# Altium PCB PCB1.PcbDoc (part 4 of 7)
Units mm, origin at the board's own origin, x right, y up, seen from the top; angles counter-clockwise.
Board outline 139.9 x 46.81 mm, 2 copper layers (Top Layer, Bottom Layer); 0 components, 100 nets, 100 pads, 0 vias.
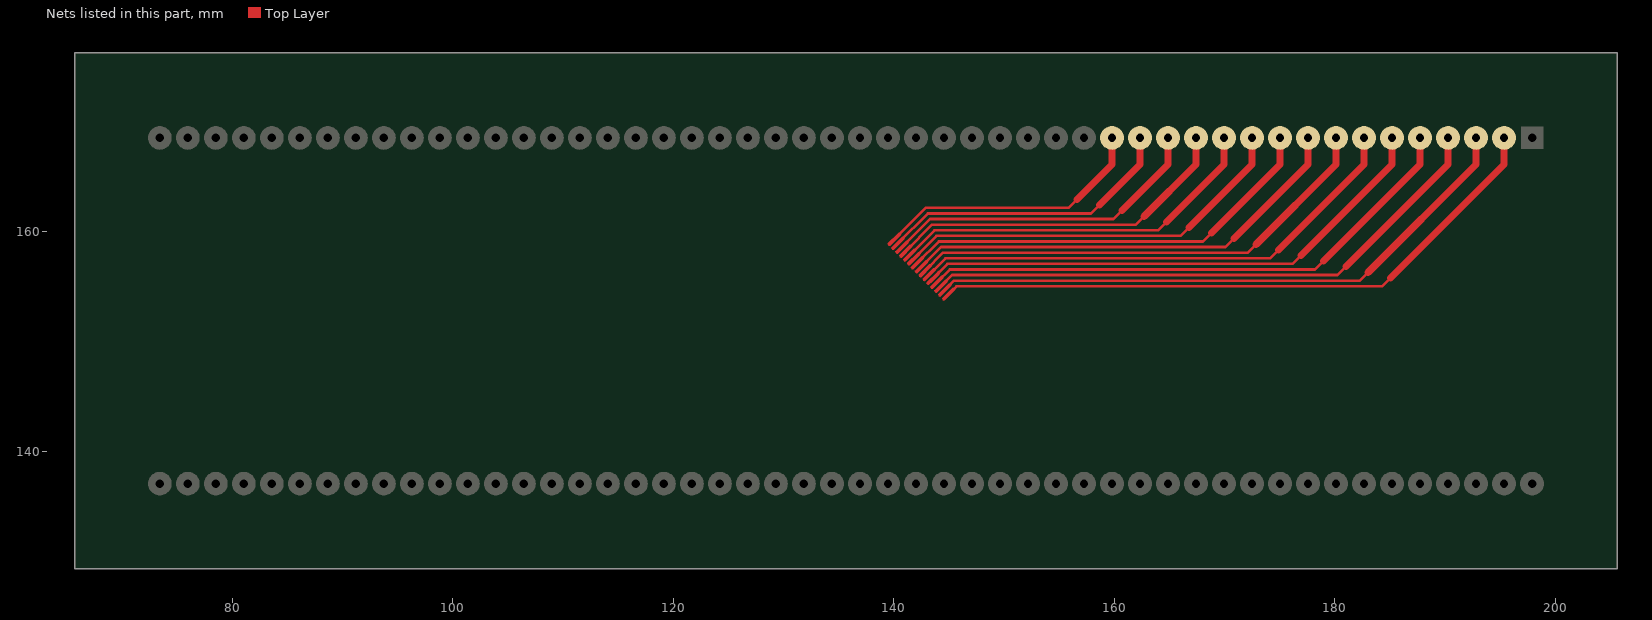
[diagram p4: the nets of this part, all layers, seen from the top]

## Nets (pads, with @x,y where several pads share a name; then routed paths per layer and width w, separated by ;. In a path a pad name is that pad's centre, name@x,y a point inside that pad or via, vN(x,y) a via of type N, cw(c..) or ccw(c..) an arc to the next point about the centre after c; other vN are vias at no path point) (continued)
$Net44: pad.1@159.787,168.455 | length 48.9
  Top Layer w0.03: 139.475,158.8 139.731,158.8 ; 139.475,158.815 139.746,158.815 ; 139.477,158.831 139.762,158.831 ; 139.48,158.785 139.716,158.785 ; 139.487,158.77 139.701,158.77 ; 139.498,158.754 139.686,158.754 ; 139.503,158.876 139.807,158.876 ; 139.51,158.739 139.67,158.739 ; 139.518,158.892 139.823,158.892 ; 139.526,158.724 139.655,158.724 ; 139.533,158.907 139.838,158.907 ; 139.548,158.709 139.637,158.709 ; 139.548,158.922 139.853,158.922 ; 139.564,158.937 139.868,158.937 ; 139.579,158.953 139.884,158.953 ; 139.594,158.968 139.899,158.968 ; 139.609,158.983 139.914,158.983 ; 139.625,158.998 139.929,158.998 ; 139.64,159.014 139.945,159.014 ; 139.655,159.029 139.96,159.029 ; 139.67,159.044 139.975,159.044 ; 139.686,159.059 139.99,159.059 ; 139.701,159.075 140.006,159.075 ; 139.716,159.09 140.021,159.09 ; 139.731,159.105 140.036,159.105 ; 139.746,159.12 140.051,159.12 ; 139.762,159.135 140.067,159.135 ; 139.777,158.846 139.48,158.846 ; 139.777,159.151 140.082,159.151 ; 139.792,158.861 139.487,158.861 ; 139.792,159.166 140.097,159.166 ; 139.807,159.181 140.115,159.181 ; 139.823,159.196 140.13,159.196 ; 139.838,159.212 140.145,159.212 ; 139.853,159.227 140.161,159.227 ; 139.868,159.242 140.176,159.242 ; 139.884,159.257 140.191,159.257 ; 139.899,159.273 140.206,159.273 ; 139.914,159.288 140.221,159.288 ; 139.929,159.303 140.237,159.303 ; 139.945,159.318 140.252,159.318 ; 139.96,159.334 140.267,159.334 ; 139.978,159.349 140.282,159.349 ; 139.993,159.364 140.298,159.364 ; 140.008,159.379 140.313,159.379 ; 140.023,159.395 140.328,159.395 ; 140.039,159.41 140.343,159.41 ; 140.054,159.425 140.359,159.425 ; 140.069,159.44 140.374,159.44 ; 140.084,159.456 140.389,159.456 ; 140.1,159.471 140.404,159.471 ; 140.115,159.486 140.42,159.486 ; 140.13,159.501 140.435,159.501 ; 140.145,159.516 140.45,159.516 ; 140.161,159.532 140.465,159.532 ; 140.176,159.547 140.481,159.547 ; 140.191,159.562 140.496,159.562 ; 140.206,159.577 140.511,159.577 ; 140.221,159.593 140.526,159.593 ; 140.237,159.608 140.542,159.608 ; 140.252,159.623 140.557,159.623 ; 140.267,159.638 140.572,159.638 ; 140.282,159.654 140.587,159.654 ; 140.298,159.669 140.597,159.669 ; 140.313,159.684 140.605,159.684 ; 140.328,159.699 140.608,159.699 ; 140.343,159.715 140.61,159.715 ; 140.359,159.73 140.608,159.73 ; 140.374,159.745 140.602,159.745 ; 140.389,159.76 140.592,159.76 ; 140.404,159.776 140.582,159.776 ; 140.42,159.791 140.567,159.791 ; 140.435,159.806 140.552,159.806 ; 140.455,159.821 140.529,159.821 ; 139.48,158.846 139.487,158.861 ; 139.48,158.846 139.472,158.813 139.475,158.795 139.48,158.78 139.5,158.749 139.528,158.721 139.559,158.701 139.574,158.696 139.592,158.694 139.625,158.701 139.637,158.709 ; 139.487,158.861 139.498,158.874 140.445,159.816 140.458,159.824 140.491,159.831 140.508,159.829 140.524,159.824 140.554,159.804 140.582,159.776 ; 139.637,158.709 140.585,159.651 140.595,159.664 140.602,159.679 140.61,159.712 140.608,159.73 ; 140.582,159.776 140.602,159.745 ; 140.602,159.745 140.608,159.73
  Top Layer w0.241: 140.041,159.262 142.881,162.105 155.85,162.105 156.612,162.867
  Top Layer w0.635: 156.612,162.867 159.787,166.042 pad.1@159.787,168.455
$Net45: pad.1@162.327,168.455 | length 51.2
  Top Layer w0.03: 139.828,158.447 140.084,158.447 ; 139.828,158.462 140.1,158.462 ; 139.83,158.478 140.115,158.478 ; 139.833,158.432 140.069,158.432 ; 139.84,158.417 140.054,158.417 ; 139.851,158.401 140.039,158.401 ; 139.856,158.523 140.161,158.523 ; 139.863,158.386 140.023,158.386 ; 139.871,158.539 140.176,158.539 ; 139.879,158.371 140.008,158.371 ; 139.886,158.554 140.191,158.554 ; 139.901,158.356 139.99,158.356 ; 139.901,158.569 140.206,158.569 ; 139.917,158.584 140.221,158.584 ; 139.932,158.6 140.237,158.6 ; 139.947,158.615 140.252,158.615 ; 139.962,158.63 140.267,158.63 ; 139.978,158.645 140.282,158.645 ; 139.993,158.661 140.298,158.661 ; 140.008,158.676 140.313,158.676 ; 140.023,158.691 140.328,158.691 ; 140.039,158.706 140.343,158.706 ; 140.054,158.721 140.359,158.721 ; 140.069,158.737 140.374,158.737 ; 140.084,158.752 140.389,158.752 ; 140.1,158.767 140.404,158.767 ; 140.115,158.782 140.42,158.782 ; 140.13,158.493 139.833,158.493 ; 140.13,158.798 140.435,158.798 ; 140.145,158.508 139.84,158.508 ; 140.145,158.813 140.45,158.813 ; 140.161,158.828 140.468,158.828 ; 140.176,158.843 140.483,158.843 ; 140.191,158.859 140.498,158.859 ; 140.206,158.874 140.514,158.874 ; 140.221,158.889 140.529,158.889 ; 140.237,158.904 140.544,158.904 ; 140.252,158.92 140.559,158.92 ; 140.267,158.935 140.575,158.935 ; 140.282,158.95 140.59,158.95 ; 140.298,158.965 140.605,158.965 ; 140.313,158.981 140.62,158.981 ; 140.331,158.996 140.635,158.996 ; 140.346,159.011 140.651,159.011 ; 140.361,159.026 140.666,159.026 ; 140.376,159.042 140.681,159.042 ; 140.392,159.057 140.696,159.057 ; 140.407,159.072 140.712,159.072 ; 140.422,159.087 140.727,159.087 ; 140.437,159.102 140.742,159.102 ; 140.453,159.118 140.757,159.118 ; 140.468,159.133 140.773,159.133 ; 140.483,159.148 140.788,159.148 ; 140.498,159.163 140.803,159.163 ; 140.514,159.179 140.818,159.179 ; 140.529,159.194 140.834,159.194 ; 140.544,159.209 140.849,159.209 ; 140.559,159.224 140.864,159.224 ; 140.575,159.24 140.879,159.24 ; 140.59,159.255 140.895,159.255 ; 140.605,159.27 140.91,159.27 ; 140.62,159.285 140.925,159.285 ; 140.635,159.301 140.94,159.301 ; 140.651,159.316 140.95,159.316 ; 140.666,159.331 140.958,159.331 ; 140.681,159.346 140.961,159.346 ; 140.696,159.362 140.963,159.362 ; 140.712,159.377 140.961,159.377 ; 140.727,159.392 140.956,159.392 ; 140.742,159.407 140.945,159.407 ; 140.757,159.423 140.935,159.423 ; 140.773,159.438 140.92,159.438 ; 140.788,159.453 140.905,159.453 ; 140.808,159.468 140.882,159.468 ; 139.833,158.493 139.84,158.508 ; 139.833,158.493 139.825,158.46 139.828,158.442 139.833,158.427 139.853,158.396 139.881,158.368 139.912,158.348 139.927,158.343 139.945,158.34 139.978,158.348 139.99,158.356 ; 139.84,158.508 139.851,158.521 140.798,159.463 140.811,159.471 140.844,159.478 140.862,159.476 140.877,159.471 140.907,159.45 140.935,159.423 ; 139.99,158.356 140.938,159.298 140.948,159.311 140.956,159.326 140.963,159.359 140.961,159.377 ; 140.935,159.423 140.956,159.392 ; 140.956,159.392 140.961,159.377
  Top Layer w0.241: 140.394,158.909 143.082,161.597 157.882,161.597 158.644,162.359
  Top Layer w0.635: 158.644,162.359 162.327,166.042 pad.1@162.327,168.455
$Net46: pad.1@164.867,168.455 | length 53.5
  Top Layer w0.03: 140.181,158.092 140.437,158.092 ; 140.181,158.107 140.453,158.107 ; 140.183,158.122 140.468,158.122 ; 140.186,158.076 140.422,158.076 ; 140.194,158.061 140.407,158.061 ; 140.204,158.046 140.392,158.046 ; 140.209,158.168 140.514,158.168 ; 140.216,158.031 140.376,158.031 ; 140.224,158.183 140.529,158.183 ; 140.232,158.015 140.361,158.015 ; 140.239,158.198 140.544,158.198 ; 140.254,158 140.343,158 ; 140.254,158.213 140.559,158.213 ; 140.27,158.229 140.575,158.229 ; 140.285,158.244 140.59,158.244 ; 140.3,158.259 140.605,158.259 ; 140.315,158.274 140.62,158.274 ; 140.331,158.29 140.635,158.29 ; 140.346,158.305 140.651,158.305 ; 140.361,158.32 140.666,158.32 ; 140.376,158.335 140.681,158.335 ; 140.392,158.351 140.696,158.351 ; 140.407,158.366 140.712,158.366 ; 140.422,158.381 140.727,158.381 ; 140.437,158.396 140.742,158.396 ; 140.453,158.412 140.757,158.412 ; 140.468,158.427 140.773,158.427 ; 140.483,158.137 140.186,158.137 ; 140.483,158.442 140.788,158.442 ; 140.498,158.153 140.194,158.153 ; 140.498,158.457 140.803,158.457 ; 140.514,158.473 140.821,158.473 ; 140.529,158.488 140.836,158.488 ; 140.544,158.503 140.851,158.503 ; 140.559,158.518 140.867,158.518 ; 140.575,158.534 140.882,158.534 ; 140.59,158.549 140.897,158.549 ; 140.605,158.564 140.912,158.564 ; 140.62,158.579 140.928,158.579 ; 140.635,158.594 140.943,158.594 ; 140.651,158.61 140.958,158.61 ; 140.666,158.625 140.973,158.625 ; 140.684,158.64 140.989,158.64 ; 140.699,158.655 141.004,158.655 ; 140.714,158.671 141.019,158.671 ; 140.729,158.686 141.034,158.686 ; 140.745,158.701 141.05,158.701 ; 140.76,158.716 141.065,158.716 ; 140.775,158.732 141.08,158.732 ; 140.79,158.747 141.095,158.747 ; 140.806,158.762 141.11,158.762 ; 140.821,158.777 141.126,158.777 ; 140.836,158.793 141.141,158.793 ; 140.851,158.808 141.156,158.808 ; 140.867,158.823 141.171,158.823 ; 140.882,158.838 141.187,158.838 ; 140.897,158.854 141.202,158.854 ; 140.912,158.869 141.217,158.869 ; 140.928,158.884 141.232,158.884 ; 140.943,158.899 141.248,158.899 ; 140.958,158.915 141.263,158.915 ; 140.973,158.93 141.278,158.93 ; 140.989,158.945 141.293,158.945 ; 141.004,158.96 141.304,158.96 ; 141.019,158.975 141.311,158.975 ; 141.034,158.991 141.314,158.991 ; 141.05,159.006 141.316,159.006 ; 141.065,159.021 141.314,159.021 ; 141.08,159.036 141.309,159.036 ; 141.095,159.052 141.298,159.052 ; 141.11,159.067 141.288,159.067 ; 141.126,159.082 141.273,159.082 ; 141.141,159.097 141.258,159.097 ; 141.161,159.113 141.235,159.113 ; 140.186,158.137 140.194,158.153 ; 140.186,158.137 140.178,158.104 140.181,158.086 140.186,158.071 140.206,158.041 140.234,158.013 140.265,157.992 140.28,157.987 140.298,157.985 140.331,157.992 140.343,158 ; 140.194,158.153 140.204,158.165 141.151,159.108 141.164,159.115 141.197,159.123 141.215,159.12 141.23,159.115 141.26,159.095 141.288,159.067 ; 140.343,158 141.291,158.942 141.301,158.955 141.309,158.97 141.316,159.003 141.314,159.021 ; 141.288,159.067 141.309,159.036 ; 141.309,159.036 141.314,159.021
  Top Layer w0.241: 140.747,158.554 143.28,161.089 159.914,161.089 160.676,161.851
  Top Layer w0.635: 160.676,161.851 164.867,166.042 pad.1@164.867,168.455
$Net47: pad.1@167.407,168.455 | length 55.9
  Top Layer w0.03: 140.534,157.738 140.79,157.738 ; 140.534,157.754 140.806,157.754 ; 140.536,157.769 140.821,157.769 ; 140.539,157.723 140.775,157.723 ; 140.547,157.708 140.76,157.708 ; 140.557,157.693 140.745,157.693 ; 140.562,157.815 140.867,157.815 ; 140.569,157.678 140.729,157.678 ; 140.577,157.83 140.882,157.83 ; 140.585,157.662 140.714,157.662 ; 140.592,157.845 140.897,157.845 ; 140.608,157.647 140.696,157.647 ; 140.608,157.86 140.912,157.86 ; 140.623,157.876 140.928,157.876 ; 140.638,157.891 140.943,157.891 ; 140.653,157.906 140.958,157.906 ; 140.669,157.921 140.973,157.921 ; 140.684,157.937 140.989,157.937 ; 140.699,157.952 141.004,157.952 ; 140.714,157.967 141.019,157.967 ; 140.729,157.982 141.034,157.982 ; 140.745,157.998 141.05,157.998 ; 140.76,158.013 141.065,158.013 ; 140.775,158.028 141.08,158.028 ; 140.79,158.043 141.095,158.043 ; 140.806,158.059 141.11,158.059 ; 140.821,158.074 141.126,158.074 ; 140.836,157.784 140.539,157.784 ; 140.836,158.089 141.141,158.089 ; 140.851,157.799 140.547,157.799 ; 140.851,158.104 141.156,158.104 ; 140.867,158.119 141.174,158.119 ; 140.882,158.135 141.189,158.135 ; 140.897,158.15 141.204,158.15 ; 140.912,158.165 141.22,158.165 ; 140.928,158.18 141.235,158.18 ; 140.943,158.196 141.25,158.196 ; 140.958,158.211 141.265,158.211 ; 140.973,158.226 141.281,158.226 ; 140.989,158.241 141.296,158.241 ; 141.004,158.257 141.311,158.257 ; 141.019,158.272 141.326,158.272 ; 141.037,158.287 141.342,158.287 ; 141.052,158.302 141.357,158.302 ; 141.067,158.318 141.372,158.318 ; 141.083,158.333 141.387,158.333 ; 141.098,158.348 141.403,158.348 ; 141.113,158.363 141.418,158.363 ; 141.128,158.379 141.433,158.379 ; 141.143,158.394 141.448,158.394 ; 141.159,158.409 141.464,158.409 ; 141.174,158.424 141.479,158.424 ; 141.189,158.44 141.494,158.44 ; 141.204,158.455 141.509,158.455 ; 141.22,158.47 141.524,158.47 ; 141.235,158.485 141.54,158.485 ; 141.25,158.5 141.555,158.5 ; 141.265,158.516 141.57,158.516 ; 141.281,158.531 141.585,158.531 ; 141.296,158.546 141.601,158.546 ; 141.311,158.561 141.616,158.561 ; 141.326,158.577 141.631,158.577 ; 141.342,158.592 141.646,158.592 ; 141.357,158.607 141.657,158.607 ; 141.372,158.622 141.664,158.622 ; 141.387,158.638 141.667,158.638 ; 141.403,158.653 141.669,158.653 ; 141.418,158.668 141.667,158.668 ; 141.433,158.683 141.662,158.683 ; 141.448,158.699 141.651,158.699 ; 141.464,158.714 141.641,158.714 ; 141.479,158.729 141.626,158.729 ; 141.494,158.744 141.611,158.744 ; 141.514,158.76 141.588,158.76 ; 140.539,157.784 140.547,157.799 ; 140.539,157.784 140.531,157.751 140.534,157.733 140.539,157.718 140.559,157.688 140.587,157.66 140.618,157.639 140.633,157.634 140.651,157.632 140.684,157.639 140.696,157.647 ; 140.547,157.799 140.557,157.812 141.504,158.754 141.517,158.762 141.55,158.77 141.568,158.767 141.583,158.762 141.613,158.742 141.641,158.714 ; 140.696,157.647 141.644,158.589 141.654,158.602 141.662,158.617 141.669,158.65 141.667,158.668 ; 141.641,158.714 141.662,158.683 ; 141.662,158.683 141.667,158.668
  Top Layer w0.241: 141.1,158.201 143.48,160.581 161.946,160.581 162.708,161.343
  Top Layer w0.635: 162.708,161.343 167.407,166.042 pad.1@167.407,168.455
$Net48: pad.1@169.947,168.455 | length 58.2
  Top Layer w0.03: 140.887,157.385 141.143,157.385 ; 140.887,157.401 141.159,157.401 ; 140.889,157.416 141.174,157.416 ; 140.892,157.37 141.128,157.37 ; 140.9,157.355 141.113,157.355 ; 140.91,157.34 141.098,157.34 ; 140.915,157.462 141.22,157.462 ; 140.923,157.324 141.083,157.324 ; 140.93,157.477 141.235,157.477 ; 140.938,157.309 141.067,157.309 ; 140.945,157.492 141.25,157.492 ; 140.961,157.294 141.05,157.294 ; 140.961,157.507 141.265,157.507 ; 140.976,157.523 141.281,157.523 ; 140.991,157.538 141.296,157.538 ; 141.006,157.553 141.311,157.553 ; 141.022,157.568 141.326,157.568 ; 141.037,157.584 141.342,157.584 ; 141.052,157.599 141.357,157.599 ; 141.067,157.614 141.372,157.614 ; 141.083,157.629 141.387,157.629 ; 141.098,157.645 141.403,157.645 ; 141.113,157.66 141.418,157.66 ; 141.128,157.675 141.433,157.675 ; 141.143,157.69 141.448,157.69 ; 141.159,157.705 141.464,157.705 ; 141.174,157.721 141.479,157.721 ; 141.189,157.431 140.892,157.431 ; 141.189,157.736 141.494,157.736 ; 141.204,157.446 140.9,157.446 ; 141.204,157.751 141.509,157.751 ; 141.22,157.766 141.527,157.766 ; 141.235,157.782 141.542,157.782 ; 141.25,157.797 141.558,157.797 ; 141.265,157.812 141.573,157.812 ; 141.281,157.827 141.588,157.827 ; 141.296,157.843 141.603,157.843 ; 141.311,157.858 141.618,157.858 ; 141.326,157.873 141.634,157.873 ; 141.342,157.888 141.649,157.888 ; 141.357,157.904 141.664,157.904 ; 141.372,157.919 141.679,157.919 ; 141.39,157.934 141.695,157.934 ; 141.405,157.949 141.71,157.949 ; 141.42,157.965 141.725,157.965 ; 141.436,157.98 141.74,157.98 ; 141.451,157.995 141.756,157.995 ; 141.466,158.01 141.771,158.01 ; 141.481,158.026 141.786,158.026 ; 141.497,158.041 141.801,158.041 ; 141.512,158.056 141.817,158.056 ; 141.527,158.071 141.832,158.071 ; 141.542,158.086 141.847,158.086 ; 141.558,158.102 141.862,158.102 ; 141.573,158.117 141.878,158.117 ; 141.588,158.132 141.893,158.132 ; 141.603,158.147 141.908,158.147 ; 141.618,158.163 141.923,158.163 ; 141.634,158.178 141.939,158.178 ; 141.649,158.193 141.954,158.193 ; 141.664,158.208 141.969,158.208 ; 141.679,158.224 141.984,158.224 ; 141.695,158.239 141.999,158.239 ; 141.71,158.254 142.01,158.254 ; 141.725,158.269 142.017,158.269 ; 141.74,158.285 142.02,158.285 ; 141.756,158.3 142.022,158.3 ; 141.771,158.315 142.02,158.315 ; 141.786,158.33 142.015,158.33 ; 141.801,158.346 142.005,158.346 ; 141.817,158.361 141.994,158.361 ; 141.832,158.376 141.979,158.376 ; 141.847,158.391 141.964,158.391 ; 141.867,158.407 141.941,158.407 ; 140.892,157.431 140.9,157.446 ; 140.892,157.431 140.884,157.398 140.887,157.38 140.892,157.365 140.912,157.335 140.94,157.307 140.971,157.286 140.986,157.281 141.004,157.279 141.037,157.286 141.05,157.294 ; 140.9,157.446 140.91,157.459 141.857,158.401 141.87,158.409 141.903,158.417 141.921,158.414 141.936,158.409 141.966,158.389 141.994,158.361 ; 141.05,157.294 141.997,158.236 142.007,158.249 142.015,158.264 142.022,158.297 142.02,158.315 ; 141.994,158.361 142.015,158.33 ; 142.015,158.33 142.02,158.315
  Top Layer w0.241: 141.453,157.848 143.678,160.073 163.978,160.073 164.74,160.835
  Top Layer w0.635: 164.74,160.835 169.947,166.042 pad.1@169.947,168.455
$Net49: pad.1@172.487,168.455 | length 60.5
  Top Layer w0.03: 141.243,157.032 141.499,157.032 ; 141.243,157.048 141.514,157.048 ; 141.245,157.063 141.53,157.063 ; 141.248,157.017 141.484,157.017 ; 141.255,157.002 141.469,157.002 ; 141.265,156.987 141.453,156.987 ; 141.27,157.109 141.575,157.109 ; 141.278,156.971 141.438,156.971 ; 141.286,157.124 141.591,157.124 ; 141.293,156.956 141.423,156.956 ; 141.301,157.139 141.606,157.139 ; 141.316,156.941 141.405,156.941 ; 141.316,157.154 141.621,157.154 ; 141.331,157.17 141.636,157.17 ; 141.347,157.185 141.651,157.185 ; 141.362,157.2 141.667,157.2 ; 141.377,157.215 141.682,157.215 ; 141.392,157.23 141.697,157.23 ; 141.408,157.246 141.712,157.246 ; 141.423,157.261 141.728,157.261 ; 141.438,157.276 141.743,157.276 ; 141.453,157.291 141.758,157.291 ; 141.469,157.307 141.773,157.307 ; 141.484,157.322 141.789,157.322 ; 141.499,157.337 141.804,157.337 ; 141.514,157.352 141.819,157.352 ; 141.53,157.368 141.834,157.368 ; 141.545,157.078 141.248,157.078 ; 141.545,157.383 141.85,157.383 ; 141.56,157.093 141.255,157.093 ; 141.56,157.398 141.865,157.398 ; 141.575,157.413 141.883,157.413 ; 141.591,157.429 141.898,157.429 ; 141.606,157.444 141.913,157.444 ; 141.621,157.459 141.928,157.459 ; 141.636,157.474 141.944,157.474 ; 141.651,157.49 141.959,157.49 ; 141.667,157.505 141.974,157.505 ; 141.682,157.52 141.989,157.52 ; 141.697,157.535 142.005,157.535 ; 141.712,157.551 142.02,157.551 ; 141.728,157.566 142.035,157.566 ; 141.745,157.581 142.05,157.581 ; 141.761,157.596 142.066,157.596 ; 141.776,157.611 142.081,157.611 ; 141.791,157.627 142.096,157.627 ; 141.806,157.642 142.111,157.642 ; 141.822,157.657 142.126,157.657 ; 141.837,157.672 142.142,157.672 ; 141.852,157.688 142.157,157.688 ; 141.867,157.703 142.172,157.703 ; 141.883,157.718 142.187,157.718 ; 141.898,157.733 142.203,157.733 ; 141.913,157.749 142.218,157.749 ; 141.928,157.764 142.233,157.764 ; 141.944,157.779 142.248,157.779 ; 141.959,157.794 142.264,157.794 ; 141.974,157.81 142.279,157.81 ; 141.989,157.825 142.294,157.825 ; 142.005,157.84 142.309,157.84 ; 142.02,157.855 142.325,157.855 ; 142.035,157.871 142.34,157.871 ; 142.05,157.886 142.355,157.886 ; 142.066,157.901 142.365,157.901 ; 142.081,157.916 142.373,157.916 ; 142.096,157.932 142.375,157.932 ; 142.111,157.947 142.378,157.947 ; 142.126,157.962 142.375,157.962 ; 142.142,157.977 142.37,157.977 ; 142.157,157.992 142.36,157.992 ; 142.172,158.008 142.35,158.008 ; 142.187,158.023 142.335,158.023 ; 142.203,158.038 142.32,158.038 ; 142.223,158.053 142.297,158.053 ; 141.248,157.078 141.255,157.093 ; 141.248,157.078 141.24,157.045 141.243,157.027 141.248,157.012 141.268,156.982 141.296,156.954 141.326,156.933 141.342,156.928 141.359,156.926 141.392,156.933 141.405,156.941 ; 141.255,157.093 141.265,157.106 142.213,158.048 142.226,158.056 142.259,158.064 142.276,158.061 142.292,158.056 142.322,158.036 142.35,158.008 ; 141.405,156.941 142.353,157.883 142.363,157.896 142.37,157.911 142.378,157.944 142.375,157.962 ; 142.35,158.008 142.37,157.977 ; 142.37,157.977 142.375,157.962
  Top Layer w0.241: 141.809,157.495 143.877,159.565 166.01,159.565 166.772,160.327
  Top Layer w0.635: 166.772,160.327 172.487,166.042 pad.1@172.487,168.455
$Net50: pad.1@175.025,168.455 | length 62.9
  Top Layer w0.03: 141.596,156.679 141.852,156.679 ; 141.596,156.695 141.867,156.695 ; 141.598,156.71 141.883,156.71 ; 141.601,156.664 141.837,156.664 ; 141.608,156.649 141.822,156.649 ; 141.618,156.634 141.806,156.634 ; 141.624,156.756 141.928,156.756 ; 141.631,156.618 141.791,156.618 ; 141.639,156.771 141.944,156.771 ; 141.646,156.603 141.776,156.603 ; 141.654,156.786 141.959,156.786 ; 141.669,156.588 141.758,156.588 ; 141.669,156.801 141.974,156.801 ; 141.685,156.816 141.989,156.816 ; 141.7,156.832 142.005,156.832 ; 141.715,156.847 142.02,156.847 ; 141.73,156.862 142.035,156.862 ; 141.745,156.877 142.05,156.877 ; 141.761,156.893 142.066,156.893 ; 141.776,156.908 142.081,156.908 ; 141.791,156.923 142.096,156.923 ; 141.806,156.938 142.111,156.938 ; 141.822,156.954 142.126,156.954 ; 141.837,156.969 142.142,156.969 ; 141.852,156.984 142.157,156.984 ; 141.867,156.999 142.172,156.999 ; 141.883,157.015 142.187,157.015 ; 141.898,156.725 141.601,156.725 ; 141.898,157.03 142.203,157.03 ; 141.913,156.74 141.608,156.74 ; 141.913,157.045 142.218,157.045 ; 141.928,157.06 142.236,157.06 ; 141.944,157.076 142.251,157.076 ; 141.959,157.091 142.266,157.091 ; 141.974,157.106 142.281,157.106 ; 141.989,157.121 142.297,157.121 ; 142.005,157.137 142.312,157.137 ; 142.02,157.152 142.327,157.152 ; 142.035,157.167 142.342,157.167 ; 142.05,157.182 142.358,157.182 ; 142.066,157.197 142.373,157.197 ; 142.081,157.213 142.388,157.213 ; 142.099,157.228 142.403,157.228 ; 142.114,157.243 142.419,157.243 ; 142.129,157.258 142.434,157.258 ; 142.144,157.274 142.449,157.274 ; 142.159,157.289 142.464,157.289 ; 142.175,157.304 142.48,157.304 ; 142.19,157.319 142.495,157.319 ; 142.205,157.335 142.51,157.335 ; 142.22,157.35 142.525,157.35 ; 142.236,157.365 142.54,157.365 ; 142.251,157.38 142.556,157.38 ; 142.266,157.396 142.571,157.396 ; 142.281,157.411 142.586,157.411 ; 142.297,157.426 142.601,157.426 ; 142.312,157.441 142.617,157.441 ; 142.327,157.457 142.632,157.457 ; 142.342,157.472 142.647,157.472 ; 142.358,157.487 142.662,157.487 ; 142.373,157.502 142.678,157.502 ; 142.388,157.518 142.693,157.518 ; 142.403,157.533 142.708,157.533 ; 142.419,157.548 142.718,157.548 ; 142.434,157.563 142.726,157.563 ; 142.449,157.578 142.728,157.578 ; 142.464,157.594 142.731,157.594 ; 142.48,157.609 142.728,157.609 ; 142.495,157.624 142.723,157.624 ; 142.51,157.639 142.713,157.639 ; 142.525,157.655 142.703,157.655 ; 142.54,157.67 142.688,157.67 ; 142.556,157.685 142.673,157.685 ; 142.576,157.7 142.65,157.7 ; 141.601,156.725 141.608,156.74 ; 141.601,156.725 141.593,156.692 141.596,156.674 141.601,156.659 141.621,156.629 141.649,156.601 141.679,156.58 141.695,156.575 141.712,156.573 141.745,156.58 141.758,156.588 ; 141.608,156.74 141.618,156.753 142.566,157.695 142.579,157.703 142.612,157.711 142.629,157.708 142.645,157.703 142.675,157.683 142.703,157.655 ; 141.758,156.588 142.706,157.53 142.716,157.543 142.723,157.558 142.731,157.591 142.728,157.609 ; 142.703,157.655 142.723,157.624 ; 142.723,157.624 142.728,157.609
  Top Layer w0.241: 142.162,157.142 144.077,159.057 168.042,159.057 168.804,159.819
  Top Layer w0.635: 168.804,159.819 175.025,166.042 pad.1@175.025,168.455
$Net51: pad.1@177.565,168.455 | length 65.2
  Top Layer w0.03: 141.949,156.326 142.205,156.326 ; 141.949,156.341 142.22,156.341 ; 141.951,156.357 142.236,156.357 ; 141.954,156.311 142.19,156.311 ; 141.961,156.296 142.175,156.296 ; 141.972,156.281 142.159,156.281 ; 141.977,156.402 142.281,156.402 ; 141.984,156.265 142.144,156.265 ; 141.992,156.418 142.297,156.418 ; 141.999,156.25 142.129,156.25 ; 142.007,156.433 142.312,156.433 ; 142.022,156.235 142.111,156.235 ; 142.022,156.448 142.327,156.448 ; 142.038,156.463 142.342,156.463 ; 142.053,156.479 142.358,156.479 ; 142.068,156.494 142.373,156.494 ; 142.083,156.509 142.388,156.509 ; 142.099,156.524 142.403,156.524 ; 142.114,156.54 142.419,156.54 ; 142.129,156.555 142.434,156.555 ; 142.144,156.57 142.449,156.57 ; 142.159,156.585 142.464,156.585 ; 142.175,156.601 142.48,156.601 ; 142.19,156.616 142.495,156.616 ; 142.205,156.631 142.51,156.631 ; 142.22,156.646 142.525,156.646 ; 142.236,156.662 142.54,156.662 ; 142.251,156.372 141.954,156.372 ; 142.251,156.677 142.556,156.677 ; 142.266,156.387 141.961,156.387 ; 142.266,156.692 142.571,156.692 ; 142.281,156.707 142.589,156.707 ; 142.297,156.722 142.604,156.722 ; 142.312,156.738 142.619,156.738 ; 142.327,156.753 142.634,156.753 ; 142.342,156.768 142.65,156.768 ; 142.358,156.783 142.665,156.783 ; 142.373,156.799 142.68,156.799 ; 142.388,156.814 142.695,156.814 ; 142.403,156.829 142.711,156.829 ; 142.419,156.844 142.726,156.844 ; 142.434,156.86 142.741,156.86 ; 142.452,156.875 142.756,156.875 ; 142.467,156.89 142.772,156.89 ; 142.482,156.905 142.787,156.905 ; 142.497,156.921 142.802,156.921 ; 142.513,156.936 142.817,156.936 ; 142.528,156.951 142.833,156.951 ; 142.543,156.966 142.848,156.966 ; 142.558,156.982 142.863,156.982 ; 142.574,156.997 142.878,156.997 ; 142.589,157.012 142.894,157.012 ; 142.604,157.027 142.909,157.027 ; 142.619,157.043 142.924,157.043 ; 142.634,157.058 142.939,157.058 ; 142.65,157.073 142.955,157.073 ; 142.665,157.088 142.97,157.088 ; 142.68,157.103 142.985,157.103 ; 142.695,157.119 143,157.119 ; 142.711,157.134 143.015,157.134 ; 142.726,157.149 143.031,157.149 ; 142.741,157.164 143.046,157.164 ; 142.756,157.18 143.061,157.18 ; 142.772,157.195 143.071,157.195 ; 142.787,157.21 143.079,157.21 ; 142.802,157.225 143.082,157.225 ; 142.817,157.241 143.084,157.241 ; 142.833,157.256 143.082,157.256 ; 142.848,157.271 143.076,157.271 ; 142.863,157.286 143.066,157.286 ; 142.878,157.302 143.056,157.302 ; 142.894,157.317 143.041,157.317 ; 142.909,157.332 143.026,157.332 ; 142.929,157.347 143.003,157.347 ; 141.954,156.372 141.961,156.387 ; 141.954,156.372 141.946,156.339 141.949,156.321 141.954,156.306 141.974,156.275 142.002,156.248 142.032,156.227 142.048,156.222 142.066,156.22 142.099,156.227 142.111,156.235 ; 141.961,156.387 141.972,156.4 142.919,157.342 142.932,157.35 142.965,157.357 142.982,157.355 142.998,157.35 143.028,157.33 143.056,157.302 ; 142.111,156.235 143.059,157.177 143.069,157.19 143.076,157.205 143.084,157.238 143.082,157.256 ; 143.056,157.302 143.076,157.271 ; 143.076,157.271 143.082,157.256
  Top Layer w0.241: 142.515,156.789 144.275,158.549 170.074,158.549 170.836,159.311
  Top Layer w0.635: 170.836,159.311 177.565,166.042 pad.1@177.565,168.455
$Net52: pad.1@180.105,168.455 | length 67.5
  Top Layer w0.03: 142.302,155.971 142.558,155.971 ; 142.302,155.986 142.574,155.986 ; 142.304,156.001 142.589,156.001 ; 142.307,155.955 142.543,155.955 ; 142.314,155.94 142.528,155.94 ; 142.325,155.925 142.513,155.925 ; 142.33,156.047 142.634,156.047 ; 142.337,155.91 142.497,155.91 ; 142.345,156.062 142.65,156.062 ; 142.353,155.894 142.482,155.894 ; 142.36,156.077 142.665,156.077 ; 142.375,155.879 142.464,155.879 ; 142.375,156.093 142.68,156.093 ; 142.391,156.108 142.695,156.108 ; 142.406,156.123 142.711,156.123 ; 142.421,156.138 142.726,156.138 ; 142.436,156.154 142.741,156.154 ; 142.452,156.169 142.756,156.169 ; 142.467,156.184 142.772,156.184 ; 142.482,156.199 142.787,156.199 ; 142.497,156.214 142.802,156.214 ; 142.513,156.23 142.817,156.23 ; 142.528,156.245 142.833,156.245 ; 142.543,156.26 142.848,156.26 ; 142.558,156.275 142.863,156.275 ; 142.574,156.291 142.878,156.291 ; 142.589,156.306 142.894,156.306 ; 142.604,156.016 142.307,156.016 ; 142.604,156.321 142.909,156.321 ; 142.619,156.032 142.314,156.032 ; 142.619,156.336 142.924,156.336 ; 142.634,156.352 142.942,156.352 ; 142.65,156.367 142.957,156.367 ; 142.665,156.382 142.972,156.382 ; 142.68,156.397 142.988,156.397 ; 142.695,156.413 143.003,156.413 ; 142.711,156.428 143.018,156.428 ; 142.726,156.443 143.033,156.443 ; 142.741,156.458 143.048,156.458 ; 142.756,156.474 143.064,156.474 ; 142.772,156.489 143.079,156.489 ; 142.787,156.504 143.094,156.504 ; 142.805,156.519 143.109,156.519 ; 142.82,156.535 143.125,156.535 ; 142.835,156.55 143.14,156.55 ; 142.85,156.565 143.155,156.565 ; 142.866,156.58 143.17,156.58 ; 142.881,156.595 143.186,156.595 ; 142.896,156.611 143.201,156.611 ; 142.911,156.626 143.216,156.626 ; 142.927,156.641 143.231,156.641 ; 142.942,156.656 143.247,156.656 ; 142.957,156.672 143.262,156.672 ; 142.972,156.687 143.277,156.687 ; 142.988,156.702 143.292,156.702 ; 143.003,156.717 143.308,156.717 ; 143.018,156.733 143.323,156.733 ; 143.033,156.748 143.338,156.748 ; 143.048,156.763 143.353,156.763 ; 143.064,156.778 143.369,156.778 ; 143.079,156.794 143.384,156.794 ; 143.094,156.809 143.399,156.809 ; 143.109,156.824 143.414,156.824 ; 143.125,156.839 143.424,156.839 ; 143.14,156.855 143.432,156.855 ; 143.155,156.87 143.435,156.87 ; 143.17,156.885 143.437,156.885 ; 143.186,156.9 143.435,156.9 ; 143.201,156.916 143.429,156.916 ; 143.216,156.931 143.419,156.931 ; 143.231,156.946 143.409,156.946 ; 143.247,156.961 143.394,156.961 ; 143.262,156.976 143.379,156.976 ; 143.282,156.992 143.356,156.992 ; 142.307,156.016 142.314,156.032 ; 142.307,156.016 142.299,155.983 142.302,155.966 142.307,155.95 142.327,155.92 142.355,155.892 142.386,155.872 142.401,155.867 142.419,155.864 142.452,155.872 142.464,155.879 ; 142.314,156.032 142.325,156.044 143.272,156.987 143.285,156.994 143.318,157.002 143.336,156.999 143.351,156.994 143.381,156.974 143.409,156.946 ; 142.464,155.879 143.412,156.822 143.422,156.834 143.429,156.849 143.437,156.883 143.435,156.9 ; 143.409,156.946 143.429,156.916 ; 143.429,156.916 143.435,156.9
  Top Layer w0.241: 142.868,156.433 144.473,158.041 172.106,158.041 172.868,158.803
  Top Layer w0.635: 172.868,158.803 180.105,166.042 pad.1@180.105,168.455
$Net53: pad.1@182.645,168.455 | length 69.9
  Top Layer w0.03: 142.655,155.618 142.911,155.618 ; 142.655,155.633 142.927,155.633 ; 142.657,155.648 142.942,155.648 ; 142.66,155.602 142.896,155.602 ; 142.667,155.587 142.881,155.587 ; 142.678,155.572 142.866,155.572 ; 142.683,155.694 142.988,155.694 ; 142.69,155.557 142.85,155.557 ; 142.698,155.709 143.003,155.709 ; 142.706,155.541 142.835,155.541 ; 142.713,155.724 143.018,155.724 ; 142.728,155.526 142.817,155.526 ; 142.728,155.74 143.033,155.74 ; 142.744,155.755 143.048,155.755 ; 142.759,155.77 143.064,155.77 ; 142.774,155.785 143.079,155.785 ; 142.789,155.8 143.094,155.8 ; 142.805,155.816 143.109,155.816 ; 142.82,155.831 143.125,155.831 ; 142.835,155.846 143.14,155.846 ; 142.85,155.861 143.155,155.861 ; 142.866,155.877 143.17,155.877 ; 142.881,155.892 143.186,155.892 ; 142.896,155.907 143.201,155.907 ; 142.911,155.922 143.216,155.922 ; 142.927,155.938 143.231,155.938 ; 142.942,155.953 143.247,155.953 ; 142.957,155.663 142.66,155.663 ; 142.957,155.968 143.262,155.968 ; 142.972,155.679 142.667,155.679 ; 142.972,155.983 143.277,155.983 ; 142.988,155.999 143.295,155.999 ; 143.003,156.014 143.31,156.014 ; 143.018,156.029 143.325,156.029 ; 143.033,156.044 143.341,156.044 ; 143.048,156.06 143.356,156.06 ; 143.064,156.075 143.371,156.075 ; 143.079,156.09 143.386,156.09 ; 143.094,156.105 143.402,156.105 ; 143.109,156.121 143.417,156.121 ; 143.125,156.136 143.432,156.136 ; 143.14,156.151 143.447,156.151 ; 143.158,156.166 143.463,156.166 ; 143.173,156.181 143.478,156.181 ; 143.188,156.197 143.493,156.197 ; 143.203,156.212 143.508,156.212 ; 143.219,156.227 143.523,156.227 ; 143.234,156.242 143.539,156.242 ; 143.249,156.258 143.554,156.258 ; 143.264,156.273 143.569,156.273 ; 143.28,156.288 143.584,156.288 ; 143.295,156.303 143.6,156.303 ; 143.31,156.319 143.615,156.319 ; 143.325,156.334 143.63,156.334 ; 143.341,156.349 143.645,156.349 ; 143.356,156.364 143.661,156.364 ; 143.371,156.38 143.676,156.38 ; 143.386,156.395 143.691,156.395 ; 143.402,156.41 143.706,156.41 ; 143.417,156.425 143.722,156.425 ; 143.432,156.441 143.737,156.441 ; 143.447,156.456 143.752,156.456 ; 143.463,156.471 143.767,156.471 ; 143.478,156.486 143.777,156.486 ; 143.493,156.502 143.785,156.502 ; 143.508,156.517 143.788,156.517 ; 143.523,156.532 143.79,156.532 ; 143.539,156.547 143.788,156.547 ; 143.554,156.562 143.783,156.562 ; 143.569,156.578 143.772,156.578 ; 143.584,156.593 143.762,156.593 ; 143.6,156.608 143.747,156.608 ; 143.615,156.623 143.732,156.623 ; 143.635,156.639 143.709,156.639 ; 142.66,155.663 142.667,155.679 ; 142.66,155.663 142.652,155.63 142.655,155.613 142.66,155.597 142.68,155.567 142.708,155.539 142.739,155.519 142.754,155.513 142.772,155.511 142.805,155.519 142.817,155.526 ; 142.667,155.679 142.678,155.691 143.625,156.634 143.638,156.641 143.671,156.649 143.689,156.646 143.704,156.641 143.734,156.621 143.762,156.593 ; 142.817,155.526 143.765,156.468 143.775,156.481 143.783,156.496 143.79,156.529 143.788,156.547 ; 143.762,156.593 143.783,156.562 ; 143.783,156.562 143.788,156.547
  Top Layer w0.241: 143.221,156.08 144.674,157.533 174.138,157.533 174.9,158.295
  Top Layer w0.635: 174.9,158.295 182.645,166.042 pad.1@182.645,168.455
$Net54: pad.1@185.185,168.455 | length 72.2
  Top Layer w0.03: 143.008,155.265 143.264,155.265 ; 143.008,155.28 143.28,155.28 ; 143.01,155.295 143.295,155.295 ; 143.013,155.249 143.249,155.249 ; 143.021,155.234 143.234,155.234 ; 143.031,155.219 143.219,155.219 ; 143.036,155.341 143.341,155.341 ; 143.043,155.204 143.203,155.204 ; 143.051,155.356 143.356,155.356 ; 143.059,155.188 143.188,155.188 ; 143.066,155.371 143.371,155.371 ; 143.082,155.173 143.17,155.173 ; 143.082,155.386 143.386,155.386 ; 143.097,155.402 143.402,155.402 ; 143.112,155.417 143.417,155.417 ; 143.127,155.432 143.432,155.432 ; 143.142,155.447 143.447,155.447 ; 143.158,155.463 143.463,155.463 ; 143.173,155.478 143.478,155.478 ; 143.188,155.493 143.493,155.493 ; 143.203,155.508 143.508,155.508 ; 143.219,155.524 143.523,155.524 ; 143.234,155.539 143.539,155.539 ; 143.249,155.554 143.554,155.554 ; 143.264,155.569 143.569,155.569 ; 143.28,155.585 143.584,155.585 ; 143.295,155.6 143.6,155.6 ; 143.31,155.31 143.013,155.31 ; 143.31,155.615 143.615,155.615 ; 143.325,155.325 143.021,155.325 ; 143.325,155.63 143.63,155.63 ; 143.341,155.646 143.648,155.646 ; 143.356,155.661 143.663,155.661 ; 143.371,155.676 143.678,155.676 ; 143.386,155.691 143.694,155.691 ; 143.402,155.706 143.709,155.706 ; 143.417,155.722 143.724,155.722 ; 143.432,155.737 143.739,155.737 ; 143.447,155.752 143.755,155.752 ; 143.463,155.767 143.77,155.767 ; 143.478,155.783 143.785,155.783 ; 143.493,155.798 143.8,155.798 ; 143.511,155.813 143.816,155.813 ; 143.526,155.828 143.831,155.828 ; 143.541,155.844 143.846,155.844 ; 143.556,155.859 143.861,155.859 ; 143.572,155.874 143.877,155.874 ; 143.587,155.889 143.892,155.889 ; 143.602,155.905 143.907,155.905 ; 143.617,155.92 143.922,155.92 ; 143.633,155.935 143.937,155.935 ; 143.648,155.95 143.953,155.95 ; 143.663,155.966 143.968,155.966 ; 143.678,155.981 143.983,155.981 ; 143.694,155.996 143.998,155.996 ; 143.709,156.011 144.014,156.011 ; 143.724,156.027 144.029,156.027 ; 143.739,156.042 144.044,156.042 ; 143.755,156.057 144.059,156.057 ; 143.77,156.072 144.075,156.072 ; 143.785,156.087 144.09,156.087 ; 143.8,156.103 144.105,156.103 ; 143.816,156.118 144.12,156.118 ; 143.831,156.133 144.131,156.133 ; 143.846,156.148 144.138,156.148 ; 143.861,156.164 144.141,156.164 ; 143.877,156.179 144.143,156.179 ; 143.892,156.194 144.141,156.194 ; 143.907,156.209 144.136,156.209 ; 143.922,156.225 144.125,156.225 ; 143.937,156.24 144.115,156.24 ; 143.953,156.255 144.1,156.255 ; 143.968,156.27 144.085,156.27 ; 143.988,156.286 144.062,156.286 ; 143.013,155.31 143.021,155.325 ; 143.013,155.31 143.005,155.277 143.008,155.259 143.013,155.244 143.033,155.214 143.061,155.186 143.092,155.165 143.107,155.16 143.125,155.158 143.158,155.165 143.17,155.173 ; 143.021,155.325 143.031,155.338 143.978,156.281 143.991,156.288 144.024,156.296 144.042,156.293 144.057,156.288 144.087,156.268 144.115,156.24 ; 143.17,155.173 144.118,156.115 144.128,156.128 144.136,156.143 144.143,156.176 144.141,156.194 ; 144.115,156.24 144.136,156.209 ; 144.136,156.209 144.141,156.194
  Top Layer w0.241: 143.574,155.727 144.872,157.025 176.168,157.025 176.93,157.787
  Top Layer w0.635: 176.93,157.787 185.185,166.042 pad.1@185.185,168.455
$Net55: pad.1@187.725,168.455 | length 74.5
  Top Layer w0.03: 143.363,154.911 143.62,154.911 ; 143.363,154.927 143.635,154.927 ; 143.366,154.942 143.65,154.942 ; 143.369,154.896 143.605,154.896 ; 143.376,154.881 143.59,154.881 ; 143.386,154.866 143.574,154.866 ; 143.391,154.988 143.696,154.988 ; 143.399,154.851 143.559,154.851 ; 143.407,155.003 143.711,155.003 ; 143.414,154.835 143.544,154.835 ; 143.422,155.018 143.727,155.018 ; 143.437,154.82 143.526,154.82 ; 143.437,155.033 143.742,155.033 ; 143.452,155.049 143.757,155.049 ; 143.468,155.064 143.772,155.064 ; 143.483,155.079 143.788,155.079 ; 143.498,155.094 143.803,155.094 ; 143.513,155.11 143.818,155.11 ; 143.529,155.125 143.833,155.125 ; 143.544,155.14 143.849,155.14 ; 143.559,155.155 143.864,155.155 ; 143.574,155.171 143.879,155.171 ; 143.59,155.186 143.894,155.186 ; 143.605,155.201 143.91,155.201 ; 143.62,155.216 143.925,155.216 ; 143.635,155.232 143.94,155.232 ; 143.65,155.247 143.955,155.247 ; 143.666,154.957 143.369,154.957 ; 143.666,155.262 143.971,155.262 ; 143.681,154.972 143.376,154.972 ; 143.681,155.277 143.986,155.277 ; 143.696,155.292 144.004,155.292 ; 143.711,155.308 144.019,155.308 ; 143.727,155.323 144.034,155.323 ; 143.742,155.338 144.049,155.338 ; 143.757,155.353 144.064,155.353 ; 143.772,155.369 144.08,155.369 ; 143.788,155.384 144.095,155.384 ; 143.803,155.399 144.11,155.399 ; 143.818,155.414 144.125,155.414 ; 143.833,155.43 144.141,155.43 ; 143.849,155.445 144.156,155.445 ; 143.866,155.46 144.171,155.46 ; 143.882,155.475 144.186,155.475 ; 143.897,155.491 144.202,155.491 ; 143.912,155.506 144.217,155.506 ; 143.927,155.521 144.232,155.521 ; 143.943,155.536 144.247,155.536 ; 143.958,155.552 144.263,155.552 ; 143.973,155.567 144.278,155.567 ; 143.988,155.582 144.293,155.582 ; 144.004,155.597 144.308,155.597 ; 144.019,155.613 144.324,155.613 ; 144.034,155.628 144.339,155.628 ; 144.049,155.643 144.354,155.643 ; 144.064,155.658 144.369,155.658 ; 144.08,155.673 144.385,155.673 ; 144.095,155.689 144.4,155.689 ; 144.11,155.704 144.415,155.704 ; 144.125,155.719 144.43,155.719 ; 144.141,155.734 144.445,155.734 ; 144.156,155.75 144.461,155.75 ; 144.171,155.765 144.476,155.765 ; 144.186,155.78 144.486,155.78 ; 144.202,155.795 144.494,155.795 ; 144.217,155.811 144.496,155.811 ; 144.232,155.826 144.499,155.826 ; 144.247,155.841 144.496,155.841 ; 144.263,155.856 144.491,155.856 ; 144.278,155.872 144.481,155.872 ; 144.293,155.887 144.471,155.887 ; 144.308,155.902 144.456,155.902 ; 144.324,155.917 144.44,155.917 ; 144.344,155.933 144.418,155.933 ; 143.369,154.957 143.376,154.972 ; 143.369,154.957 143.361,154.924 143.363,154.906 143.369,154.891 143.389,154.861 143.417,154.833 143.447,154.812 143.463,154.807 143.48,154.805 143.513,154.812 143.526,154.82 ; 143.376,154.972 143.386,154.985 144.334,155.927 144.346,155.935 144.379,155.943 144.397,155.94 144.412,155.935 144.443,155.915 144.471,155.887 ; 143.526,154.82 144.473,155.762 144.484,155.775 144.491,155.79 144.499,155.823 144.496,155.841 ; 144.471,155.887 144.491,155.856 ; 144.491,155.856 144.496,155.841
  Top Layer w0.241: 143.93,155.374 145.073,156.517 178.2,156.517 178.962,157.279
  Top Layer w0.635: 178.962,157.279 187.725,166.042 pad.1@187.725,168.455
$Net56: pad.1@190.265,168.455 | length 76.9
  Top Layer w0.03: 143.717,154.558 143.973,154.558 ; 143.717,154.574 143.988,154.574 ; 143.719,154.589 144.004,154.589 ; 143.722,154.543 143.958,154.543 ; 143.729,154.528 143.943,154.528 ; 143.739,154.513 143.927,154.513 ; 143.744,154.635 144.049,154.635 ; 143.752,154.497 143.912,154.497 ; 143.76,154.65 144.064,154.65 ; 143.767,154.482 143.897,154.482 ; 143.775,154.665 144.08,154.665 ; 143.79,154.467 143.879,154.467 ; 143.79,154.68 144.095,154.68 ; 143.805,154.696 144.11,154.696 ; 143.821,154.711 144.125,154.711 ; 143.836,154.726 144.141,154.726 ; 143.851,154.741 144.156,154.741 ; 143.866,154.757 144.171,154.757 ; 143.882,154.772 144.186,154.772 ; 143.897,154.787 144.202,154.787 ; 143.912,154.802 144.217,154.802 ; 143.927,154.817 144.232,154.817 ; 143.943,154.833 144.247,154.833 ; 143.958,154.848 144.263,154.848 ; 143.973,154.863 144.278,154.863 ; 143.988,154.878 144.293,154.878 ; 144.004,154.894 144.308,154.894 ; 144.019,154.604 143.722,154.604 ; 144.019,154.909 144.324,154.909 ; 144.034,154.619 143.729,154.619 ; 144.034,154.924 144.339,154.924 ; 144.049,154.939 144.357,154.939 ; 144.064,154.955 144.372,154.955 ; 144.08,154.97 144.387,154.97 ; 144.095,154.985 144.402,154.985 ; 144.11,155 144.418,155 ; 144.125,155.016 144.433,155.016 ; 144.141,155.031 144.448,155.031 ; 144.156,155.046 144.463,155.046 ; 144.171,155.061 144.479,155.061 ; 144.186,155.077 144.494,155.077 ; 144.202,155.092 144.509,155.092 ; 144.219,155.107 144.524,155.107 ; 144.235,155.122 144.539,155.122 ; 144.25,155.138 144.555,155.138 ; 144.265,155.153 144.57,155.153 ; 144.28,155.168 144.585,155.168 ; 144.296,155.183 144.6,155.183 ; 144.311,155.198 144.616,155.198 ; 144.326,155.214 144.631,155.214 ; 144.341,155.229 144.646,155.229 ; 144.357,155.244 144.661,155.244 ; 144.372,155.259 144.677,155.259 ; 144.387,155.275 144.692,155.275 ; 144.402,155.29 144.707,155.29 ; 144.418,155.305 144.722,155.305 ; 144.433,155.32 144.738,155.32 ; 144.448,155.336 144.753,155.336 ; 144.463,155.351 144.768,155.351 ; 144.479,155.366 144.783,155.366 ; 144.494,155.381 144.799,155.381 ; 144.509,155.397 144.814,155.397 ; 144.524,155.412 144.829,155.412 ; 144.539,155.427 144.839,155.427 ; 144.555,155.442 144.847,155.442 ; 144.57,155.458 144.849,155.458 ; 144.585,155.473 144.852,155.473 ; 144.6,155.488 144.849,155.488 ; 144.616,155.503 144.844,155.503 ; 144.631,155.519 144.834,155.519 ; 144.646,155.534 144.824,155.534 ; 144.661,155.549 144.809,155.549 ; 144.677,155.564 144.793,155.564 ; 144.697,155.579 144.771,155.579 ; 143.722,154.604 143.729,154.619 ; 143.722,154.604 143.714,154.571 143.717,154.553 143.722,154.538 143.742,154.508 143.77,154.48 143.8,154.459 143.816,154.454 143.833,154.452 143.866,154.459 143.879,154.467 ; 143.729,154.619 143.739,154.632 144.687,155.574 144.699,155.582 144.733,155.59 144.75,155.587 144.766,155.582 144.796,155.562 144.824,155.534 ; 143.879,154.467 144.826,155.409 144.837,155.422 144.844,155.437 144.852,155.47 144.849,155.488 ; 144.824,155.534 144.844,155.503 ; 144.844,155.503 144.849,155.488
  Top Layer w0.241: 144.283,155.021 145.271,156.009 180.232,156.009 180.994,156.771
  Top Layer w0.635: 180.994,156.771 190.265,166.042 pad.1@190.265,168.455
$Net57: pad.1@192.805,168.455 | length 79.2
  Top Layer w0.03: 144.07,154.203 144.326,154.203 ; 144.07,154.218 144.341,154.218 ; 144.072,154.233 144.357,154.233 ; 144.075,154.188 144.311,154.188 ; 144.082,154.172 144.296,154.172 ; 144.092,154.157 144.28,154.157 ; 144.098,154.279 144.402,154.279 ; 144.105,154.142 144.265,154.142 ; 144.113,154.294 144.418,154.294 ; 144.12,154.127 144.25,154.127 ; 144.128,154.309 144.433,154.309 ; 144.143,154.111 144.232,154.111 ; 144.143,154.325 144.448,154.325 ; 144.158,154.34 144.463,154.34 ; 144.174,154.355 144.479,154.355 ; 144.189,154.37 144.494,154.37 ; 144.204,154.386 144.509,154.386 ; 144.219,154.401 144.524,154.401 ; 144.235,154.416 144.539,154.416 ; 144.25,154.431 144.555,154.431 ; 144.265,154.447 144.57,154.447 ; 144.28,154.462 144.585,154.462 ; 144.296,154.477 144.6,154.477 ; 144.311,154.492 144.616,154.492 ; 144.326,154.508 144.631,154.508 ; 144.341,154.523 144.646,154.523 ; 144.357,154.538 144.661,154.538 ; 144.372,154.249 144.075,154.249 ; 144.372,154.553 144.677,154.553 ; 144.387,154.264 144.082,154.264 ; 144.387,154.569 144.692,154.569 ; 144.402,154.584 144.71,154.584 ; 144.418,154.599 144.725,154.599 ; 144.433,154.614 144.74,154.614 ; 144.448,154.63 144.755,154.63 ; 144.463,154.645 144.771,154.645 ; 144.479,154.66 144.786,154.66 ; 144.494,154.675 144.801,154.675 ; 144.509,154.69 144.816,154.69 ; 144.524,154.706 144.832,154.706 ; 144.539,154.721 144.847,154.721 ; 144.555,154.736 144.862,154.736 ; 144.572,154.751 144.877,154.751 ; 144.588,154.767 144.893,154.767 ; 144.603,154.782 144.908,154.782 ; 144.618,154.797 144.923,154.797 ; 144.633,154.812 144.938,154.812 ; 144.649,154.828 144.953,154.828 ; 144.664,154.843 144.969,154.843 ; 144.679,154.858 144.984,154.858 ; 144.694,154.873 144.999,154.873 ; 144.71,154.889 145.014,154.889 ; 144.725,154.904 145.03,154.904 ; 144.74,154.919 145.045,154.919 ; 144.755,154.934 145.06,154.934 ; 144.771,154.95 145.075,154.95 ; 144.786,154.965 145.091,154.965 ; 144.801,154.98 145.106,154.98 ; 144.816,154.995 145.121,154.995 ; 144.832,155.011 145.136,155.011 ; 144.847,155.026 145.152,155.026 ; 144.862,155.041 145.167,155.041 ; 144.877,155.056 145.182,155.056 ; 144.893,155.071 145.192,155.071 ; 144.908,155.087 145.2,155.087 ; 144.923,155.102 145.202,155.102 ; 144.938,155.117 145.205,155.117 ; 144.953,155.132 145.202,155.132 ; 144.969,155.148 145.197,155.148 ; 144.984,155.163 145.187,155.163 ; 144.999,155.178 145.177,155.178 ; 145.014,155.193 145.162,155.193 ; 145.03,155.209 145.147,155.209 ; 145.05,155.224 145.124,155.224 ; 144.075,154.249 144.082,154.264 ; 144.075,154.249 144.067,154.216 144.07,154.198 144.075,154.182 144.095,154.152 144.123,154.124 144.153,154.104 144.169,154.099 144.186,154.096 144.219,154.104 144.232,154.111 ; 144.082,154.264 144.092,154.276 145.04,155.219 145.053,155.226 145.086,155.234 145.103,155.232 145.119,155.226 145.149,155.206 145.177,155.178 ; 144.232,154.111 145.18,155.054 145.19,155.066 145.197,155.082 145.205,155.115 145.202,155.132 ; 145.177,155.178 145.197,155.148 ; 145.197,155.148 145.202,155.132
  Top Layer w0.241: 144.636,154.665 145.469,155.501 182.264,155.501 183.026,156.263
  Top Layer w0.635: 183.026,156.263 192.805,166.042 pad.1@192.805,168.455
$Net58: pad.1@195.345,168.455 | length 81.5
  Top Layer w0.03: 144.423,153.85 144.679,153.85 ; 144.423,153.865 144.694,153.865 ; 144.425,153.88 144.71,153.88 ; 144.428,153.835 144.664,153.835 ; 144.435,153.819 144.649,153.819 ; 144.445,153.804 144.633,153.804 ; 144.451,153.926 144.755,153.926 ; 144.458,153.789 144.618,153.789 ; 144.466,153.941 144.771,153.941 ; 144.473,153.774 144.603,153.774 ; 144.481,153.956 144.786,153.956 ; 144.496,153.758 144.585,153.758 ; 144.496,153.972 144.801,153.972 ; 144.512,153.987 144.816,153.987 ; 144.527,154.002 144.832,154.002 ; 144.542,154.017 144.847,154.017 ; 144.557,154.033 144.862,154.033 ; 144.572,154.048 144.877,154.048 ; 144.588,154.063 144.893,154.063 ; 144.603,154.078 144.908,154.078 ; 144.618,154.094 144.923,154.094 ; 144.633,154.109 144.938,154.109 ; 144.649,154.124 144.953,154.124 ; 144.664,154.139 144.969,154.139 ; 144.679,154.155 144.984,154.155 ; 144.694,154.17 144.999,154.17 ; 144.71,154.185 145.014,154.185 ; 144.725,153.895 144.428,153.895 ; 144.725,154.2 145.03,154.2 ; 144.74,153.911 144.435,153.911 ; 144.74,154.216 145.045,154.216 ; 144.755,154.231 145.063,154.231 ; 144.771,154.246 145.078,154.246 ; 144.786,154.261 145.093,154.261 ; 144.801,154.276 145.108,154.276 ; 144.816,154.292 145.124,154.292 ; 144.832,154.307 145.139,154.307 ; 144.847,154.322 145.154,154.322 ; 144.862,154.337 145.169,154.337 ; 144.877,154.353 145.185,154.353 ; 144.893,154.368 145.2,154.368 ; 144.908,154.383 145.215,154.383 ; 144.926,154.398 145.23,154.398 ; 144.941,154.414 145.246,154.414 ; 144.956,154.429 145.261,154.429 ; 144.971,154.444 145.276,154.444 ; 144.987,154.459 145.291,154.459 ; 145.002,154.475 145.307,154.475 ; 145.017,154.49 145.322,154.49 ; 145.032,154.505 145.337,154.505 ; 145.047,154.52 145.352,154.52 ; 145.063,154.536 145.368,154.536 ; 145.078,154.551 145.383,154.551 ; 145.093,154.566 145.398,154.566 ; 145.108,154.581 145.413,154.581 ; 145.124,154.597 145.428,154.597 ; 145.139,154.612 145.444,154.612 ; 145.154,154.627 145.459,154.627 ; 145.169,154.642 145.474,154.642 ; 145.185,154.657 145.489,154.657 ; 145.2,154.673 145.505,154.673 ; 145.215,154.688 145.52,154.688 ; 145.23,154.703 145.535,154.703 ; 145.246,154.718 145.545,154.718 ; 145.261,154.734 145.553,154.734 ; 145.276,154.749 145.555,154.749 ; 145.291,154.764 145.558,154.764 ; 145.307,154.779 145.555,154.779 ; 145.322,154.795 145.55,154.795 ; 145.337,154.81 145.54,154.81 ; 145.352,154.825 145.53,154.825 ; 145.368,154.84 145.515,154.84 ; 145.383,154.856 145.5,154.856 ; 145.403,154.871 145.477,154.871 ; 144.428,153.895 144.435,153.911 ; 144.428,153.895 144.42,153.862 144.423,153.845 144.428,153.829 144.448,153.799 144.476,153.771 144.506,153.751 144.522,153.746 144.539,153.743 144.572,153.751 144.585,153.758 ; 144.435,153.911 144.445,153.923 145.393,154.866 145.406,154.873 145.439,154.881 145.456,154.878 145.472,154.873 145.502,154.853 145.53,154.825 ; 144.585,153.758 145.533,154.701 145.543,154.713 145.55,154.729 145.558,154.762 145.555,154.779 ; 145.53,154.825 145.55,154.795 ; 145.55,154.795 145.555,154.779
  Top Layer w0.241: 144.989,154.312 145.67,154.993 184.296,154.993 185.058,155.755
  Top Layer w0.635: 185.058,155.755 195.345,166.042 pad.1@195.345,168.455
